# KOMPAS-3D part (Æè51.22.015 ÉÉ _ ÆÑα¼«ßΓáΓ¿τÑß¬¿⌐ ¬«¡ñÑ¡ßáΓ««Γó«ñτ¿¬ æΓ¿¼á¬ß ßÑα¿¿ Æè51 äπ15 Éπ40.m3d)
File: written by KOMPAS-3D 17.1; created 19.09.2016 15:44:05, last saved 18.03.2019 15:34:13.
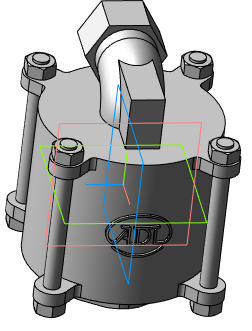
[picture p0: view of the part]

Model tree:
1. Операция без истории:2  (labels: Сталь 20  ГОСТ 1050-88; ТК51.22.015)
